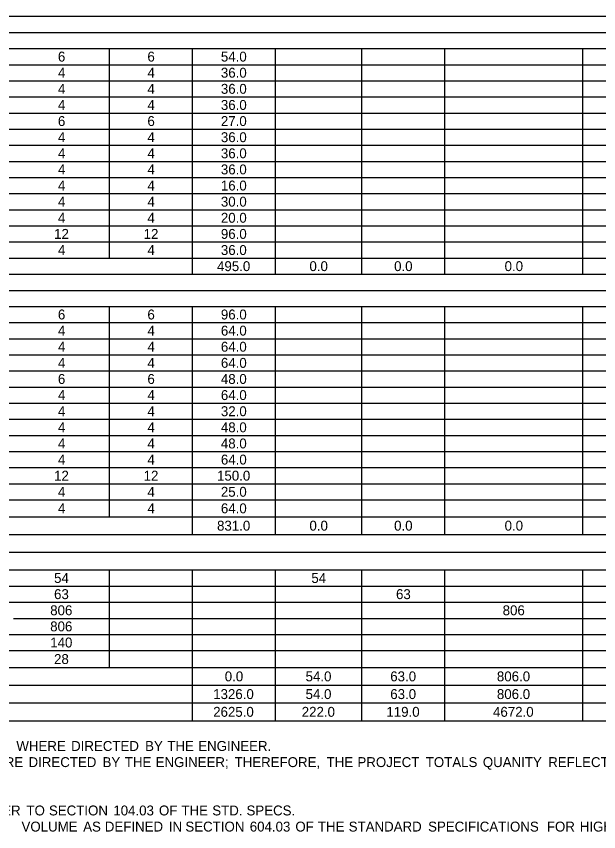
# Model space of a CAD drawing. Extents: x 540541 to 1930787, y -1948574 to 596640.
# Drawn here: x 541023.9 to 541375.9, y -1947042 to -1946548.8 of the extents above; entities that cross this region are included whole.
import ezdxf

# ---------------------------------------------------------------- set-up
doc = ezdxf.new("R2010")
doc.units = 0
doc.layers.add('Default', color=7, linetype='Continuous')

msp = doc.modelspace()

# ---------------------------------------------------------------- linework, layer by layer
at = {"layer": 'Default'}
for p, q in [((540553.71, -1946548.83), (541684.22, -1946548.83)), ((540553.71, -1946558.58), (541684.22, -1946558.58)), ((540553.71, -1946568.33), (541684.22, -1946568.33)), ((541080.21, -1946695.08), (541080.21, -1946568.33)), ((541130.42, -1946695.08), (541130.42, -1946568.33)), ((541130.42, -1946704.83), (541130.42, -1946568.33)), ((541180.63, -1946704.83), (541180.63, -1946568.33)), ((541180.63, -1946704.83), (541180.63, -1946568.33)), ((541232.8, -1946704.83), (541232.8, -1946568.33)), ((541232.8, -1946704.83), (541232.8, -1946568.33)), ((541283.01, -1946704.83), (541283.01, -1946568.33)), ((541283.01, -1946704.83), (541283.01, -1946568.33)), ((541366.37, -1946704.83), (541366.37, -1946568.33)), ((541366.37, -1946704.83), (541366.37, -1946568.33)), ((540553.71, -1946578.08), (541684.22, -1946578.08)), ((540553.71, -1946587.83), (541684.22, -1946587.83)), ((540553.71, -1946597.58), (541684.22, -1946597.58)), ((540553.71, -1946607.33), (541684.22, -1946607.33)), ((540553.71, -1946617.08), (541684.22, -1946617.08)), ((540553.71, -1946626.83), (541684.22, -1946626.83)), ((540553.71, -1946636.58), (541684.22, -1946636.58)), ((540553.71, -1946646.33), (541684.22, -1946646.33)), ((540553.71, -1946656.08), (541684.22, -1946656.08)), ((540553.71, -1946665.83), (541684.22, -1946665.83)), ((540553.71, -1946675.58), (541684.22, -1946675.58)), ((540553.71, -1946685.33), (541684.22, -1946685.33)), ((540871.56, -1946695.08), (541180.63, -1946695.08)), ((541022.2, -1946695.08), (541130.42, -1946695.08)), ((541130.42, -1946695.08), (541180.63, -1946695.08)), ((541180.63, -1946695.08), (541684.22, -1946695.08)), ((540553.71, -1946704.83), (541684.22, -1946704.83)), ((540553.71, -1946714.58), (541684.22, -1946714.58)), ((540553.71, -1946724.33), (541684.22, -1946724.33)), ((541080.21, -1946851.56), (541080.21, -1946724.33)), ((541130.42, -1946862.29), (541130.42, -1946724.33)), ((541130.42, -1946862.29), (541130.42, -1946724.33)), ((541180.63, -1946862.29), (541180.63, -1946724.33)), ((541180.63, -1946862.29), (541180.63, -1946724.33)), ((541232.8, -1946862.29), (541232.8, -1946724.33)), ((541232.8, -1946862.29), (541232.8, -1946724.33)), ((541283.01, -1946862.29), (541283.01, -1946724.33)), ((541283.01, -1946862.29), (541283.01, -1946724.33)), ((541366.37, -1946862.29), (541366.37, -1946724.33)), ((541366.37, -1946862.29), (541366.37, -1946724.33)), ((540553.71, -1946734.08), (541684.22, -1946734.08)), ((540553.71, -1946743.83), (541684.22, -1946743.83)), ((540553.71, -1946753.58), (541684.22, -1946753.58)), ((540553.71, -1946763.33), (541684.22, -1946763.33)), ((540553.71, -1946773.08), (541684.22, -1946773.08)), ((540553.71, -1946782.83), (541684.22, -1946782.83)), ((540553.71, -1946792.58), (541684.22, -1946792.58)), ((540553.71, -1946802.33), (541684.22, -1946802.33)), ((540553.71, -1946812.08), (541684.22, -1946812.08)), ((540553.71, -1946821.83), (541684.22, -1946821.83)), ((540553.71, -1946831.58), (541684.22, -1946831.58)), ((540553.71, -1946841.33), (541684.22, -1946841.33)), ((540553.71, -1946851.56), (541684.22, -1946851.56)), ((540553.71, -1946851.56), (541684.22, -1946851.56)), ((540553.71, -1946862.29), (541684.22, -1946862.29)), ((540553.71, -1946873.01), (541684.22, -1946873.01)), ((540553.71, -1946883.74), (541684.22, -1946883.74)), ((541080.21, -1946942.73), (541080.21, -1946883.74)), ((541130.42, -1946974.9), (541130.42, -1946883.74)), ((541130.42, -1946974.9), (541130.42, -1946883.74)), ((541180.63, -1946974.9), (541180.63, -1946883.74)), ((541180.63, -1946974.9), (541180.63, -1946883.74)), ((541232.8, -1946974.9), (541232.8, -1946883.74)), ((541232.8, -1946974.9), (541232.8, -1946883.74)), ((541283.01, -1946974.9), (541283.01, -1946883.74)), ((541283.01, -1946974.9), (541283.01, -1946883.74)), ((541366.37, -1946974.9), (541366.37, -1946883.74)), ((541366.37, -1946974.9), (541366.37, -1946883.74)), ((540553.71, -1946893.49), (541684.22, -1946893.49)), ((540553.71, -1946903.24), (541684.22, -1946903.24)), ((541022.2, -1946912.99), (541366.37, -1946912.99)), ((541080.21, -1946912.99), (541283.01, -1946912.99)), ((541283.01, -1946912.99), (541684.22, -1946912.99)), ((540553.71, -1946922.74), (541684.22, -1946922.74)), ((540553.71, -1946932.49), (541684.22, -1946932.49)), ((540553.71, -1946942.73), (541597.93, -1946942.73)), ((540553.71, -1946942.73), (541684.22, -1946942.73)), ((540553.71, -1946953.45), (541684.22, -1946953.45)), ((540553.71, -1946964.18), (541684.22, -1946964.18)), ((540553.71, -1946974.9), (541684.22, -1946974.9))]:
    msp.add_line(p, q, dxfattribs=at)

# ---------------------------------------------------------------- texts
for s, p in [('6', (541049.06, -1946576.2)), ('6', (541103.17, -1946576.2)), ('54.0', (541147.57, -1946576.2)), ('4', (541049.08, -1946585.95)), ('4', (541103.19, -1946585.95)), ('36.0', (541147.57, -1946585.95)), ('4', (541049.08, -1946595.7)), ('4', (541103.19, -1946595.7)), ('36.0', (541147.57, -1946595.7)), ('4', (541049.08, -1946605.45)), ('4', (541103.19, -1946605.45)), ('36.0', (541147.57, -1946605.45)), ('6', (541049.06, -1946615.2)), ('6', (541103.17, -1946615.2)), ('27.0', (541147.57, -1946615.2)), ('4', (541049.08, -1946624.95)), ('4', (541103.19, -1946624.95)), ('36.0', (541147.57, -1946624.95)), ('4', (541049.08, -1946634.7)), ('4', (541103.19, -1946634.7)), ('36.0', (541147.57, -1946634.7)), ('4', (541049.08, -1946644.45)), ('4', (541103.19, -1946644.45)), ('36.0', (541147.57, -1946644.45)), ('4', (541049.08, -1946654.2)), ('4', (541103.19, -1946654.2)), ('16.0', (541147.57, -1946654.2)), ('4', (541049.08, -1946663.95)), ('4', (541103.19, -1946663.95)), ('30.0', (541147.57, -1946663.95)), ('4', (541049.08, -1946673.7)), ('4', (541103.19, -1946673.7)), ('20.0', (541147.57, -1946673.7)), ('12', (541046.76, -1946683.45)), ('12', (541100.88, -1946683.45)), ('96.0', (541147.57, -1946683.45)), ('4', (541049.08, -1946693.2)), ('4', (541103.19, -1946693.2)), ('36.0', (541147.57, -1946693.2)), ('495.0', (541145.25, -1946702.95)), ('0.0', (541201.1, -1946702.95)), ('0.0', (541252.28, -1946702.95)), ('0.0', (541319.07, -1946702.95)), ('6', (541049.06, -1946732.2)), ('6', (541103.17, -1946732.2)), ('96.0', (541147.57, -1946732.2)), ('4', (541049.08, -1946741.95)), ('4', (541103.19, -1946741.95)), ('64.0', (541147.57, -1946741.95)), ('4', (541049.08, -1946751.7)), ('4', (541103.19, -1946751.7)), ('64.0', (541147.57, -1946751.7)), ('4', (541049.08, -1946761.45)), ('4', (541103.19, -1946761.45)), ('64.0', (541147.57, -1946761.45)), ('6', (541049.06, -1946771.2)), ('6', (541103.17, -1946771.2)), ('48.0', (541147.57, -1946771.2)), ('4', (541049.08, -1946780.95)), ('4', (541103.19, -1946780.95)), ('64.0', (541147.57, -1946780.95)), ('4', (541049.08, -1946790.7)), ('4', (541103.19, -1946790.7)), ('32.0', (541147.57, -1946790.7)), ('4', (541049.08, -1946800.45)), ('4', (541103.19, -1946800.45)), ('48.0', (541147.57, -1946800.45)), ('4', (541049.08, -1946810.2)), ('4', (541103.19, -1946810.2)), ('48.0', (541147.57, -1946810.2)), ('4', (541049.08, -1946819.95)), ('4', (541103.19, -1946819.95)), ('64.0', (541147.57, -1946819.95)), ('12', (541046.76, -1946829.7)), ('12', (541100.88, -1946829.7)), ('150.0', (541145.24, -1946829.7)), ('4', (541049.08, -1946839.45)), ('4', (541103.19, -1946839.45)), ('25.0', (541147.57, -1946839.45)), ('4', (541049.08, -1946849.45)), ('4', (541103.19, -1946849.45)), ('64.0', (541147.57, -1946849.45)), ('831.0', (541145.25, -1946859.93)), ('0.0', (541201.1, -1946859.93)), ('0.0', (541252.28, -1946859.93)), ('0.0', (541319.07, -1946859.93)), ('54', (541046.75, -1946891.61)), ('54', (541202.26, -1946891.61)), ('63', (541046.73, -1946901.36)), ('63', (541253.43, -1946901.36)), ('806', (541044.4, -1946911.11)), ('806', (541317.89, -1946911.11)), ('806', (541044.4, -1946920.86)), ('140', (541044.41, -1946930.61)), ('28', (541046.73, -1946940.61)), ('0.0', (541149.91, -1946951.09)), ('54.0', (541198.77, -1946951.09)), ('63.0', (541249.95, -1946951.09)), ('806.0', (541314.41, -1946951.09)), ('1326.0', (541142.92, -1946961.81)), ('54.0', (541198.77, -1946961.81)), ('63.0', (541249.95, -1946961.81)), ('806.0', (541314.41, -1946961.81)), ('2625.0', (541142.92, -1946972.54)), ('222.0', (541196.44, -1946972.54)), ('119.0', (541247.62, -1946972.54)), ('4672.0', (541312.08, -1946972.54)), (' WHERE', (541021.72, -1946993.2)), (' DIRECTED', (541054.8, -1946993.2)), (' BY', (541099.54, -1946993.2)), (' THE', (541112.99, -1946993.2)), (' ENGINEER.', (541131.64, -1946993.2)), (' WHERE', (540995.99, -1947002.95)), (' DIRECTED', (541029.08, -1947002.95)), (' BY', (541073.81, -1947002.95)), (' THE', (541087.26, -1947002.95)), (' ENGINEER;', (541105.91, -1947002.95)), (' THEREFORE,', (541153.61, -1947002.95)), (' THE', (541209.23, -1947002.95)), (' PROJECT', (541227.88, -1947002.95)), (' TOTALS', (541269.17, -1947002.95)), (' QUANITY', (541303.67, -1947002.95)), (' REFLECTS', (541343.2, -1947002.95)), ('  REFER', (540994.86, -1947032.2)), (' TO', (541027.82, -1947032.2)), (' SECTION', (541041.42, -1947032.2)), (' 104.03', (541080.33, -1947032.2)), (' OF', (541107.9, -1947032.2)), (' THE', (541121.49, -1947032.2)), (' STD.', (541140.14, -1947032.2)), (' SPECS.', (541160.83, -1947032.2)), (' VOLUME', (541024.83, -1947041.95)), (' AS', (541062.11, -1947041.95)), (' SECTION', (541123.89, -1947041.95)), (' 604.03', (541162.8, -1947041.95)), (' OF', (541190.38, -1947041.95)), (' STANDARD', (541222.61, -1947041.95)), (' SPECIFICATIONS', (541270.61, -1947041.95)), (' FOR', (541342.38, -1947041.95)), (' HIGHWAY', (541362.29, -1947041.95)), (' DEFINED', (541075.19, -1947041.95)), (' IN', (541113.87, -1947041.95)), (' THE', (541203.96, -1947041.95))]:
    msp.add_text(s, height=6, dxfattribs=at).set_placement(p)

doc.saveas('drawing.dxf')
